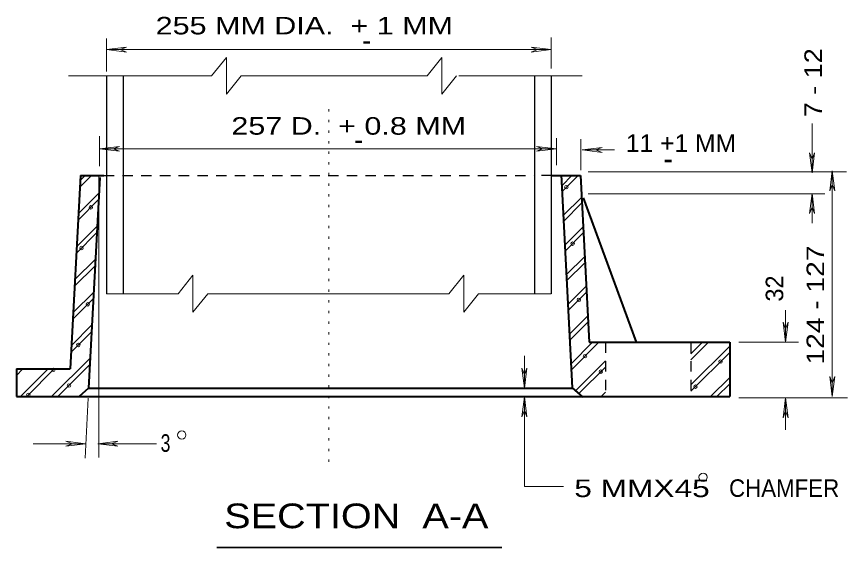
# Model space of a CAD drawing. Extents: x 312583 to 312854, y 144419 to 144597.
# Drawn here: x 312623.28 to 312659.29, y 144498.9 to 144521.91 of the extents above; entities that cross this region are included whole.
import ezdxf
from ezdxf.enums import TextEntityAlignment as Align

# ---------------------------------------------------------------- set-up
doc = ezdxf.new("R2010")
doc.units = 0
doc.header["$LTSCALE"] = 0.3
doc.header["$PDMODE"] = 32
doc.header["$PDSIZE"] = 0.15
doc.linetypes.add('DOTTED', pattern=[1.5, 0.3, -1.2])
doc.linetypes.add('SHORT_DASHED', pattern=[2.7, 1.5, -1.2])
doc.layers.add('1', color=7, linetype='Continuous', lineweight=40)
doc.layers.add('2', color=7, linetype='Continuous', lineweight=13)

msp = doc.modelspace()

# ---------------------------------------------------------------- linework, layer by layer
at = {"layer": '1', "lineweight": 13}
msp.add_line((312626.8485, 144515.0217), (312626.8485, 144502.7934), dxfattribs=at)
at = {"layer": '1', "linetype": 'SHORT_DASHED', "lineweight": 25}
for p, q in [((312627.0632, 144515.0217), (312627.8759, 144515.0217)), ((312646.4829, 144515.0217), (312645.6702, 144515.0217))]:
    msp.add_line(p, q, dxfattribs=at)
at = {"layer": '1'}
for p, q in [((312647.8322, 144514.048), (312650.1322, 144507.792)), ((312626.4039, 144505.7987), (312625.9975, 144505.4384)), ((312626.4039, 144505.814), (312626.3962, 144505.8217)), ((312647.3645, 144505.8217), (312647.8245, 144505.4077))]:
    msp.add_line(p, q, dxfattribs=at)
at = {"layer": '2'}
for p, q in [((312627.1782, 144520.9557), (312627.1782, 144519.5297)), ((312646.4522, 144521.0017), (312646.4522, 144519.6677)), ((312627.1782, 144520.4804), (312628.0445, 144520.5877)), ((312628.0445, 144520.5877), (312627.7685, 144520.4804)), ((312645.5859, 144520.5877), (312645.8619, 144520.4804)), ((312646.4522, 144520.4804), (312645.5859, 144520.5877)), ((312645.5859, 144520.5877), (312645.8619, 144520.4804)), ((312646.4522, 144520.4804), (312645.5859, 144520.5877)), ((312627.1782, 144520.4804), (312646.4522, 144520.4804)), ((312627.1782, 144520.4804), (312628.0445, 144520.373)), ((312628.0445, 144520.373), (312627.7685, 144520.4804)), ((312645.5859, 144520.373), (312645.8619, 144520.4804)), ((312646.4522, 144520.4804), (312645.5859, 144520.373)), ((312645.5859, 144520.373), (312645.8619, 144520.4804)), ((312646.4522, 144520.4804), (312645.5859, 144520.373)), ((312625.5375, 144519.3457), (312631.6095, 144519.3457)), ((312627.1782, 144519.3457), (312631.7322, 144519.3457)), ((312633.0125, 144519.3457), (312641.0319, 144519.3457)), ((312633.1045, 144519.3457), (312641.0779, 144519.3457)), ((312642.4425, 144519.3457), (312647.7862, 144519.3457)), ((312657.7529, 144515.1444), (312657.7529, 144517.282)), ((312626.8792, 144515.428), (312626.8792, 144516.7237)), ((312646.6745, 144515.474), (312646.6745, 144516.6394)), ((312647.7402, 144515.2517), (312647.7402, 144516.601)), ((312626.8792, 144516.1794), (312627.7455, 144516.2867)), ((312627.7455, 144516.2867), (312627.4695, 144516.1794)), ((312645.8082, 144516.2867), (312646.0842, 144516.1794)), ((312646.6745, 144516.1794), (312645.8082, 144516.2867)), ((312645.8082, 144516.2867), (312646.0842, 144516.1794)), ((312646.6745, 144516.1794), (312645.8082, 144516.2867)), ((312647.7862, 144516.1334), (312648.6525, 144516.2407)), ((312648.6525, 144516.2407), (312648.3765, 144516.1334)), ((312626.8792, 144516.1794), (312646.6745, 144516.1794)), ((312626.8792, 144516.1794), (312627.7455, 144516.072)), ((312627.7455, 144516.072), (312627.4695, 144516.1794)), ((312645.8082, 144516.072), (312646.0842, 144516.1794)), ((312646.6745, 144516.1794), (312645.8082, 144516.072)), ((312645.8082, 144516.072), (312646.0842, 144516.1794)), ((312646.6745, 144516.1794), (312645.8082, 144516.072)), ((312647.7862, 144516.1334), (312649.1969, 144516.1334)), ((312647.7862, 144516.1334), (312648.6525, 144516.026)), ((312648.6525, 144516.026), (312648.3765, 144516.1334)), ((312657.6455, 144516.0107), (312657.7529, 144515.7347)), ((312657.7529, 144515.1444), (312657.6455, 144516.0107)), ((312657.8602, 144516.0107), (312657.7529, 144515.7347)), ((312657.7529, 144515.1444), (312657.8602, 144516.0107)), ((312648.0545, 144515.1827), (312659.2502, 144515.1827)), ((312658.6295, 144515.2287), (312658.5222, 144514.3624)), ((312658.6295, 144505.4384), (312658.6295, 144515.2287)), ((312658.6295, 144515.2287), (312658.7368, 144514.3624)), ((312626.0205, 144514.5157), (312626.4805, 144514.9757)), ((312626.0359, 144514.807), (312626.2352, 144515.0064)), ((312646.9045, 144514.577), (312647.3569, 144515.037)), ((312646.9199, 144514.324), (312647.6252, 144515.0294)), ((312658.5222, 144514.3624), (312658.6295, 144514.6384)), ((312658.7368, 144514.3624), (312658.6295, 144514.6384)), ((312625.9592, 144513.3734), (312626.8485, 144514.2627)), ((312646.9659, 144513.289), (312647.7709, 144514.0864)), ((312648.0545, 144514.232), (312658.3049, 144514.232)), ((312657.7529, 144514.2397), (312657.6455, 144513.3734)), ((312657.7529, 144512.9631), (312657.7529, 144514.2397)), ((312657.7529, 144514.2397), (312657.8602, 144513.3734)), ((312625.9439, 144513.0897), (312626.8332, 144513.979)), ((312646.9812, 144513.036), (312647.7785, 144513.8334)), ((312657.6455, 144513.3734), (312657.7529, 144513.6494)), ((312657.8602, 144513.3734), (312657.7529, 144513.6494)), ((312625.8902, 144511.9474), (312626.7719, 144512.829)), ((312647.0349, 144512.001), (312647.8322, 144512.7984)), ((312625.8749, 144511.656), (312626.7565, 144512.5454)), ((312647.0502, 144511.748), (312647.8475, 144512.5454)), ((312625.8135, 144510.5137), (312626.7029, 144511.403)), ((312647.1039, 144510.7207), (312647.9012, 144511.5104)), ((312647.1192, 144510.46), (312647.9165, 144511.2574)), ((312625.7982, 144510.23), (312626.6875, 144511.1117)), ((312647.1729, 144509.4327), (312647.9702, 144510.2224)), ((312625.7369, 144509.0877), (312626.6262, 144509.9694)), ((312627.1782, 144509.9004), (312630.2832, 144509.9004)), ((312631.5635, 144509.9004), (312642.0132, 144509.9004)), ((312643.2935, 144509.9004), (312646.4522, 144509.9004)), ((312647.1882, 144509.172), (312647.9855, 144509.9694)), ((312625.7215, 144508.7964), (312626.6109, 144509.6857)), ((312656.6105, 144507.792), (312656.6105, 144509.1874)), ((312647.2419, 144508.1447), (312648.0392, 144508.942)), ((312647.2572, 144507.884), (312648.0545, 144508.6814)), ((312625.6602, 144507.654), (312626.5495, 144508.5434)), ((312656.5032, 144508.6584), (312656.6105, 144508.3824)), ((312656.6105, 144507.792), (312656.5032, 144508.6584)), ((312656.7179, 144508.6584), (312656.6105, 144508.3824)), ((312656.6105, 144507.792), (312656.7179, 144508.6584)), ((312625.6525, 144507.3704), (312626.5342, 144508.252)), ((312647.3109, 144506.8567), (312648.2462, 144507.792)), ((312647.3262, 144506.596), (312648.5145, 144507.792)), ((312652.5089, 144507.033), (312653.2679, 144507.792)), ((312652.5089, 144507.2937), (312653.0072, 144507.792)), ((312652.5089, 144505.952), (312654.1879, 144507.6234)), ((312654.5789, 144507.792), (312657.1702, 144507.792)), ((312652.5089, 144507.3014), (312652.5625, 144507.355)), ((312624.8015, 144505.4384), (312626.4729, 144507.1097)), ((312645.2869, 144505.8064), (312645.2869, 144507.2017)), ((312647.5025, 144505.6914), (312648.7982, 144506.987)), ((312623.2835, 144506.3584), (312623.5595, 144506.642)), ((312623.4522, 144505.4384), (312624.6482, 144506.642)), ((312623.7205, 144505.4384), (312624.9165, 144506.642)), ((312625.0699, 144505.4384), (312626.4575, 144506.826)), ((312645.1795, 144506.6727), (312645.2869, 144506.3967)), ((312645.2869, 144505.8064), (312645.1795, 144506.6727)), ((312645.3942, 144506.6727), (312645.2869, 144506.3967)), ((312645.2869, 144505.8064), (312645.3942, 144506.6727)), ((312647.6482, 144505.5687), (312648.7982, 144506.7187)), ((312653.3599, 144505.4384), (312654.1879, 144506.274)), ((312658.5222, 144506.3047), (312658.6295, 144506.0287)), ((312658.6295, 144505.4384), (312658.5222, 144506.3047)), ((312658.7368, 144506.3047), (312658.6295, 144506.0287)), ((312658.6295, 144505.4384), (312658.7368, 144506.3047)), ((312653.6282, 144505.4384), (312654.1879, 144505.998)), ((312648.5989, 144505.4307), (312648.7982, 144505.63)), ((312626.3809, 144505.3694), (312626.2505, 144502.7704)), ((312645.2869, 144505.4307), (312645.1795, 144504.5644)), ((312645.2869, 144501.5437), (312645.2869, 144505.4307)), ((312645.2869, 144505.4307), (312645.3942, 144504.5644)), ((312654.5789, 144505.3924), (312659.2861, 144505.3924)), ((312656.6105, 144505.3924), (312656.5032, 144504.526)), ((312656.6105, 144505.3924), (312656.7179, 144504.526)), ((312656.6105, 144504.0047), (312656.6105, 144505.3924)), ((312645.1795, 144504.5644), (312645.2869, 144504.8404)), ((312645.3942, 144504.5644), (312645.2869, 144504.8404)), ((312656.5032, 144504.526), (312656.6105, 144504.802)), ((312656.7179, 144504.526), (312656.6105, 144504.802)), ((312624.0042, 144503.399), (312626.2889, 144503.399)), ((312625.4225, 144503.5064), (312625.6985, 144503.399)), ((312626.2889, 144503.399), (312625.4225, 144503.5064)), ((312625.4225, 144503.2917), (312625.6985, 144503.399)), ((312626.2889, 144503.399), (312625.4225, 144503.2917)), ((312626.8102, 144503.399), (312627.6765, 144503.5064)), ((312626.8102, 144503.399), (312627.6765, 144503.5064)), ((312626.8102, 144503.399), (312629.3479, 144503.399)), ((312626.8102, 144503.399), (312627.6765, 144503.2917)), ((312626.8102, 144503.399), (312627.6765, 144503.2917)), ((312627.6765, 144503.5064), (312627.4005, 144503.399)), ((312627.6765, 144503.5064), (312627.4005, 144503.399)), ((312627.6765, 144503.2917), (312627.4005, 144503.399)), ((312627.6765, 144503.2917), (312627.4005, 144503.399)), ((312645.2869, 144501.5437), (312646.9827, 144501.5437))]:
    msp.add_line(p, q, dxfattribs=at)
at = {"layer": '2', "lineweight": 25}
for p, q in [((312627.1782, 144519.3457), (312627.1782, 144509.9004)), ((312627.8989, 144519.3457), (312627.8989, 144509.9004)), ((312645.7315, 144519.3457), (312645.7315, 144509.9004)), ((312646.4522, 144519.3457), (312646.4522, 144509.9004))]:
    msp.add_line(p, q, dxfattribs=at)
at = {"layer": '2', "linetype": 'DOTTED'}
msp.add_line((312636.8152, 144517.8967), (312636.8152, 144502.502), dxfattribs=at)
at = {"layer": '2', "lineweight": 40}
for p, q in [((312626.0512, 144515.0217), (312625.6065, 144506.642)), ((312626.0512, 144515.0217), (312627.0632, 144515.0217)), ((312626.8869, 144514.9297), (312626.4039, 144505.7987)), ((312646.4829, 144515.0217), (312647.7172, 144515.0217)), ((312646.8815, 144515.0447), (312647.3645, 144505.8217)), ((312647.7172, 144515.0217), (312648.1005, 144507.792)), ((312648.1005, 144507.792), (312654.1879, 144507.792)), ((312654.1879, 144507.792), (312654.1879, 144505.4384)), ((312623.2835, 144506.642), (312623.2835, 144505.4384)), ((312623.2835, 144506.642), (312625.6065, 144506.642)), ((312626.4039, 144505.7987), (312647.3799, 144505.7987)), ((312623.2835, 144505.4384), (312654.1879, 144505.4384))]:
    msp.add_line(p, q, dxfattribs=at)
at = {"layer": '2', "linetype": 'SHORT_DASHED', "lineweight": 25}
for p, q in [((312627.8759, 144515.0217), (312645.6702, 144515.0217)), ((312648.7982, 144507.792), (312648.7982, 144505.4384)), ((312652.5089, 144507.792), (312652.5089, 144505.4384))]:
    msp.add_line(p, q, dxfattribs=at)
at = {"layer": '2', "lineweight": 35}
msp.add_line((312631.9613, 144498.9032), (312644.3176, 144498.9032), dxfattribs=at)
at = {"layer": '2'}
for points in [[(312633.0125, 144519.3457), (312632.3762, 144518.5484), (312632.3762, 144520.143), (312631.7322, 144519.3457)], [(312642.3505, 144519.3457), (312641.7142, 144518.5484), (312641.7142, 144520.143), (312641.0702, 144519.3457)], [(312642.3505, 144519.3457), (312641.7142, 144518.5484), (312641.7142, 144520.143), (312641.0702, 144519.3457)], [(312631.5635, 144509.9004), (312630.9272, 144509.103), (312630.9272, 144510.6977), (312630.2832, 144509.9004)], [(312643.2935, 144509.9004), (312642.6572, 144509.103), (312642.6572, 144510.6977), (312642.0132, 144509.9004)], [(312652.5089, 144505.676), (312654.1879, 144507.355), (312654.1879, 144507.355)]]:
    msp.add_lwpolyline(points, dxfattribs=at)
for centre in [(312630.4421, 144503.7746), (312653.0337, 144501.9423)]:
    msp.add_circle(centre, 0.1797, dxfattribs=at)
for p in [(312647.1039, 144514.5157), (312626.5035, 144513.6417), (312626.0972, 144511.8784), (312647.3799, 144512.07), (312626.3655, 144509.4404), (312647.6482, 144509.632), (312625.9592, 144507.677), (312647.9165, 144507.194), (312653.7892, 144506.9564), (312624.8782, 144506.596), (312648.5989, 144506.5194), (312625.5529, 144505.9214), (312652.7005, 144505.8677), (312623.7895, 144505.515)]:
    msp.add_point(p, dxfattribs=at)

# ---------------------------------------------------------------- texts
for s, height, width, p in [('255 MM DIA.  + 1 MM', 0.76, 1.3, (312629.3095, 144521.1387)), ('257 D.  + 0.8 MM', 0.76, 1.3, (312632.5909, 144516.7917)), ('11 +1 MM', 0.76, 1.05, (312649.6875, 144516.048)), ('3', 0.76, 0.75, (312629.5242, 144503.0454)), ('5 MMX45   ', 0.76, 1.35, (312647.4501, 144501.0822)), ('CHAMFER', 0.76, 0.95, (312654.1579, 144501.0928)), ('SECTION  A-A', 1.07, 1.2, (312632.2801, 144499.7347))]:
    msp.add_text(s, height=height, dxfattribs=dict(at, width=width)).set_placement(p)
for p in [(312638.4525, 144520.4302), (312638.1069, 144516.1234), (312651.5138, 144515.2977)]:
    msp.add_text('-', height=0.92, dxfattribs=at).set_placement(p, align=Align.CENTER)
for s, width, p in [('7 - 12', 1.15, (312658.1832, 144517.5498)), ('124 - 127 ', 1.2, (312658.2773, 144506.831))]:
    msp.add_text(s, height=0.76, rotation=90, dxfattribs=dict(at, width=width)).set_placement(p)
msp.add_text('32', height=0.76, rotation=90, dxfattribs=at).set_placement((312656.5057, 144509.5582))

doc.saveas('drawing.dxf')
